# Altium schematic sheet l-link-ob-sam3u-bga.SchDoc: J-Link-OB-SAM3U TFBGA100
size A3; Revision: 2.0.0; SheetNumber: 2; SheetTotal: 3; DrawnBy: RUBR; ProjectNumber: 4393; PCAName: PCA10000; PCBRevision: 0100RUBR; DocumentSize: A2; PCBNumber: 400003
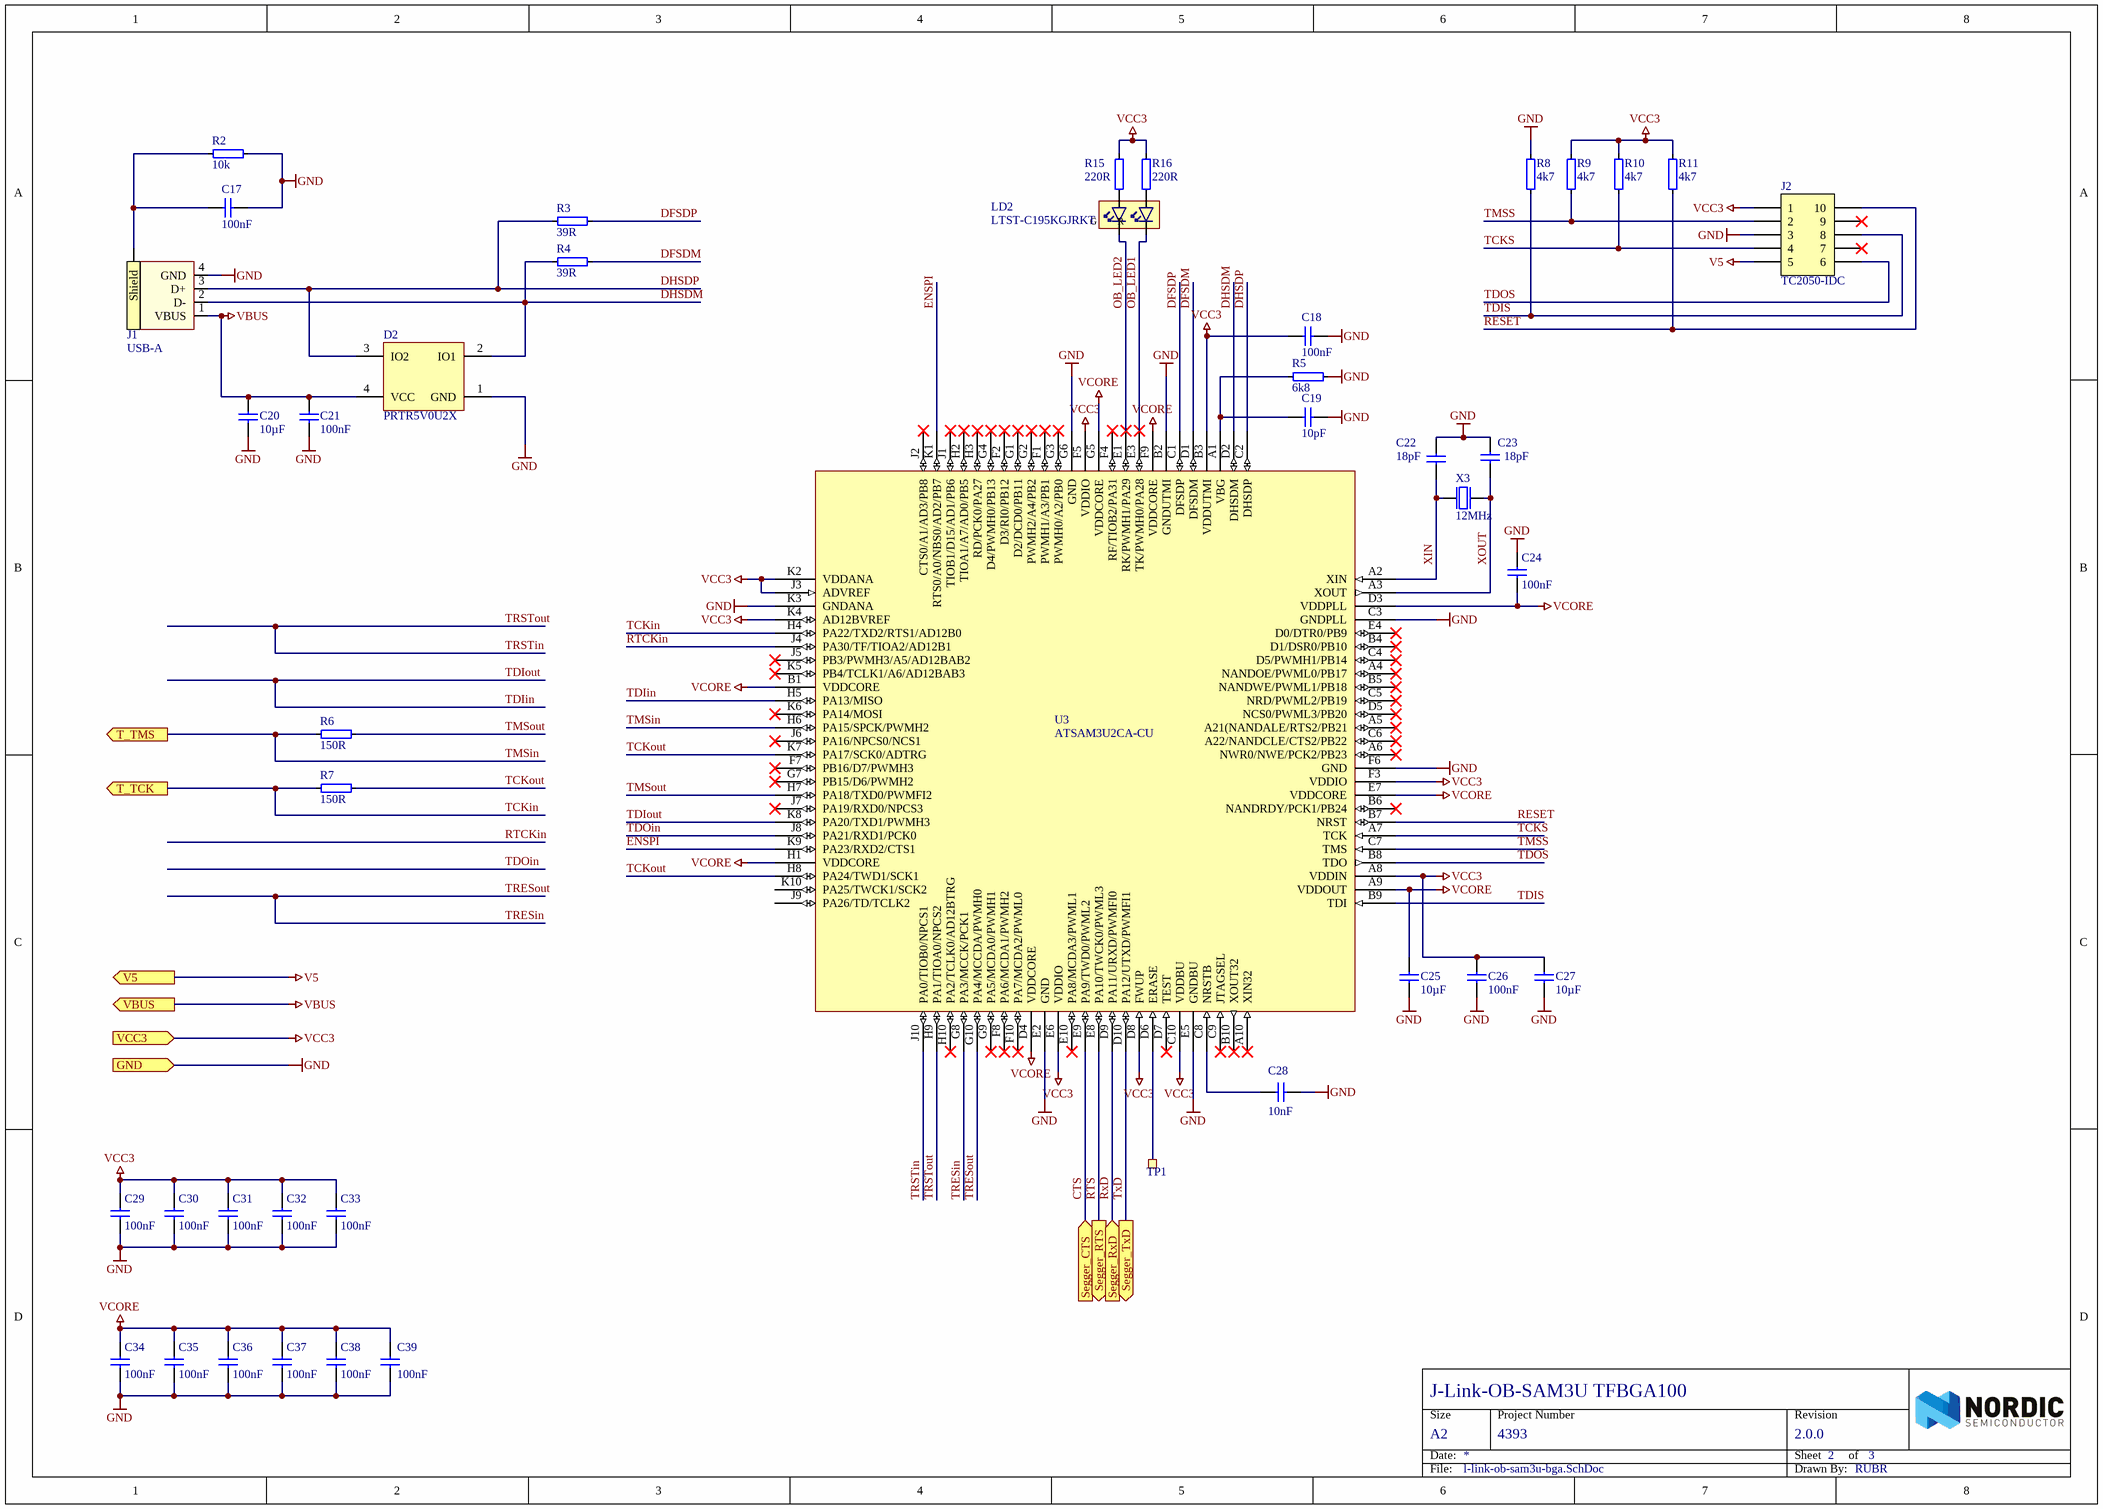
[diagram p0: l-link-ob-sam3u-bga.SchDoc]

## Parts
C17  100nF  [CAPC1005X04L]
C18  100nF  [CAPC1005X04L]
C19  10pF  [CAPC1005X04L]
C20  10µF  [CAPC1608X06L]
C21  100nF  [CAPC1005X04L]
C22  18pF  [CAPC1005X04L]
C23  18pF  [CAPC1005X04L]
C24  100nF  [CAPC1005X04L]
C25  10µF  [CAPC1608X06L]
C26  100nF  [CAPC1005X04L]
C27  10µF  [CAPC1608X06L]
C28  10nF  [CAPC1005X04L]
C29  100nF  [CAPC1005X04L]
C30  100nF  [CAPC1005X04L]
C31  100nF  [CAPC1005X04L]
C32  100nF  [CAPC1005X04L]
C33  100nF  [CAPC1005X04L]
C34  100nF  [CAPC1005X04L]
C35  100nF  [CAPC1005X04L]
C36  100nF  [CAPC1005X04L]
C37  100nF  [CAPC1005X04L]
C38  100nF  [CAPC1005X04L]
C39  100nF  [CAPC1005X04L]
D2  PRTR5V0U2X  [SOT190P230X110-4L]
J1  USB-A  [USB-PCB-A-SMD]
J2  TC2050-IDC  [TC2050-IDC-NLFP]  (no BOM)
LD2  LTST-C195KGJRKT  [LED_DUAL_0606]
R2  10k  [RESC1005X04L]
R3  39R  [RESC1005X04L]
R4  39R  [RESC1005X04L]
R5  6k8  [RESC1005X04L]
R6  150R  [RESC1005X04L]
R7  150R  [RESC1005X04L]
R8  4k7  [RESC1005X04L]
R9  4k7  [RESC1005X04L]
R10  4k7  [RESC1005X04L]
R11  4k7  [RESC1005X04L]
R15  220R  [RESC1005X04L]
R16  220R  [RESC1005X04L]
TP1  1.0mm,SMD  [TP_SMD_1.0mmX1.0mm]  (value not drawn)  (no BOM)
U3  ATSAM3U2CA-CU  [BGA100C80P10X10_900X900X110]
X3  12MHz  [BT-XTAL_3225]

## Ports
GND (in), Segger_CTS (in), Segger_RTS (out), Segger_RxD (in), Segger_TxD (out), T_TCK (out), T_TMS (out), V5 (out), VBUS (out), VCC3 (in)

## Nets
GND: C17.1 C18.1 C19.1 C20.1 C21.1 C22.2 C23.2 C24.2 C25.1 C26.1 C27.1 C28.1 C29.1 C30.1 C31.1 C32.1 C33.1 C34.1 C35.1 C36.1 C37.1 C38.1 C39.1 D2.1(GND) J1.4(GND) J2.3 R2.1 R5.1 R8.2 U3.B2(GNDUTMI) U3.C3(GNDPLL) U3.E2(GND) U3.E5(GNDBU) U3.F6(GND) U3.G6(GND) U3.K3(GNDANA) X3.2(GND) X3.4(GND) ; port GND
V5: J2.5 ; port V5
VBUS: C20.2 C21.2 D2.4(VCC) J1.1(VBUS) ; port VBUS
VCC3: C18.2 C26.2 C27.2 C29.2 C30.2 C31.2 C32.2 C33.2 J2.1 R9.2 R10.2 R11.2 R15.1 R16.1 U3.A8(VDDIN) U3.B3(VDDUTMI) U3.C10(VDDBU) U3.D8(FWUP) U3.E6(VDDIO) U3.F3(VDDIO) U3.F5(VDDIO) U3.J3(ADVREF) U3.K2(VDDANA) U3.K4(AD12BVREF) ; port VCC3
VCORE: C24.1 C25.2 C34.2 C35.2 C36.2 C37.2 C38.2 C39.2 U3.A9(VDDOUT) U3.B1(VDDCORE) U3.D3(VDDPLL) U3.D4(VDDCORE) U3.E7(VDDCORE) U3.F9(VDDCORE) U3.G5(VDDCORE) U3.H1(VDDCORE)
CTS: U3.E9(PA9/TWD0/PWML2) ; port Segger_CTS
DFSDM: R4.1 U3.D1(DFSDM)
DFSDP: R3.1 U3.C1(DFSDP)
DHSDM: D2.2(IO1) J1.2(D-) R4.2 U3.D2(DHSDM)
DHSDP: D2.3(IO2) J1.3(D+) R3.2 U3.C2(DHSDP)
ENSPI: U3.K1(RTS0/A0/NBS0/AD2/PB7) U3.K9(PA23/RXD2/CTS1)
OB_LED1: LD2.4(C1) U3.E3(TK/PWMH0/PA28)
OB_LED2: LD2.3(C2) U3.E1(RK/PWMH1/PA29)
RESET: J2.10 R11.1 U3.B7(NRST)
RTCKin: U3.J4(PA30/TF/TIOA2/AD12B1)
RTS: U3.E8(PA10/TWCK0/PWML3) ; port Segger_RTS
RxD: U3.D9(PA11/URXD/PWMFI0) ; port Segger_RxD
TCKin: R7.2 U3.H4(PA22/TXD2/RTS1/AD12B0) ; port T_TCK
TCKout: R7.1 U3.H8(PA24/TWD1/SCK1) U3.K7(PA17/SCK0/ADTRG)
TCKS: J2.4 R10.1 U3.A7(TCK)
TDIin: U3.H5(PA13/MISO) U3.K8(PA20/TXD1/PWMH3)  [also labelled TDIout]
TDIS: J2.8 R8.1 U3.B9(TDI)
TDOin: U3.J8(PA21/RXD1/PCK0)
TDOS: J2.6 U3.B8(TDO)
TMSin: R6.2 U3.H6(PA15/SPCK/PWMH2) ; port T_TMS
TMSout: R6.1 U3.H7(PA18/TXD0/PWMFI2)
TMSS: J2.2 R9.1 U3.C7(TMS)
TRESin: U3.G8(PA3/MCCK/PCK1) U3.G10(PA4/MCCDA/PWMH0)  [also labelled TRESout]
TRSTin: U3.H9(PA1/TIOA0/NPCS2) U3.J10(PA0/TIOB0/NPCS1)  [also labelled TRSTout]
TxD: U3.D10(PA12/UTXD/PWMFI1) ; port Segger_TxD
XIN: C22.1 U3.A2(XIN) X3.1(inp)
XOUT: C23.1 U3.A3(XOUT) X3.3(out)
NetC17_2: C17.2 J1.0(Shield) R2.2
NetC19_2: C19.2 R5.2 U3.A1(VBG)
NetC28_2: C28.2 U3.C8(NRSTB)
NetLD2_1: LD2.1(A2) R15.2
NetLD2_2: LD2.2(A1) R16.2
NetTP1_1: TP1.1 U3.D6(ERASE)

Not connected (* = marked no-connect by the designer): J2 7* 9*; U3 A4(NANDOE/PWML0/PB17)* A5(A21(NANDALE/RTS2/PB21)* A6(NWR0/NWE/PCK2/PB23)* A10(XIN32)* B4(D1/DSR0/PB10)* B5(NANDWE/PWML1/PB18)* B6(NANDRDY/PCK1/PB24)* B10(XOUT32)* C4(D5/PWMH1/PB14)* C5(NRD/PWML2/PB19)* C6(A22/NANDCLE/CTS2/PB22)* C9(JTAGSEL)* D5(NCS0/PWML3/PB20)* D7(TEST)* E4(D0/DTR0/PB9)* E10(PA8/MCDA3/PWML1)* F1(PWMH1/A3/PB1)* F2(D3/RI0/PB12)* F4(RF/TIOB2/PA31)* F7(PB16/D7/PWMH3)* F8(PA6/MCDA1/PWMH2)* F10(PA7/MCDA2/PWML0)* G1(D2/DCD0/PB11)* G2(PWMH2/A4/PB2)* G3(PWMH0/A2/PB0)* G4(D4/PWMH0/PB13)* G7(PB15/D6/PWMH2)* G9(PA5/MCDA0/PWMH1)* H2(TIOA1/A7/AD0/PB5)* H3(RD/PCK0/PA27)* H10(PA2/TCLK0/AD12BTRG)* J1(TIOB1/D15/AD1/PB6)* J2(CTS0/A1/AD3/PB8)* J5(PB3/PWMH3/A5/AD12BAB2)* J6(PA16/NPCS0/NCS1)* J7(PA19/RXD0/NPCS3)* J9(PA26/TD/TCLK2) K5(PB4/TCLK1/A6/AD12BAB3)* K6(PA14/MOSI)* K10(PA25/TWCK1/SCK2)

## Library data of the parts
C17 C18 C21 C24 C26 C29-C39 = C0402-100n: Capacitor, X7R, ±10%; Note: 16V; Artikkelnr Noca: 20039200
C19 = C0402-10p: Capacitor, NP0, ±2%; 2nd source part number: 185-6064; Note: 50V; Artikkelnr Noca: 20029260
C20 C25 C27 = C0603-10µ: Capacitor, X5R, ±10%; Note: 6.3V; Artikkelnr Noca: 20039252
C22 C23 = C0402-18p: Capacitor, NP0, ±5%; Note: 50V; Artikkelnr Noca: 20029209
C28 = C0402-10n: Capacitor, X7R, ±10%; Note: 16V; Artikkelnr Noca: 20039166
D2 = PRTR5V0U2X: Ultra low capacitance double rail-to-rail ESD protection diode; Manufacturer: NXP; 2nd source part number: 152-4157; Artikkelnr Noca: 10069015
J1 = Molex USB-A-SMT_w/shield: Molex USB-A-SMT; Manufacturer Part Number: 48037-1000; 2nd source part number: 538-48037-1000; Note: MOLEX - 48037-1000; Artikkelnr Noca: 55079008
J2 = TC2050-IDC-NLFP: CBL PLUG-OF-NAILS 10-PIN; Manufacturer: Tag-Connect LLC; Artikkelnr Noca: N.A.
LD2 = LTST-C195KGJRKT: Avago, HSMF-A203 Bi-Color LED; Manufacturer: Lite-On Inc; 2nd source part number: 859-LTST-C195KGJRKT; Note: HSMF-A203- xxxxx GaP Red GaP Emerald Green; Artikkelnr Noca: 13019145
R2 = R0402-10k: Resistor, ±1%, 0.063W; Note: Chip Res 1%; Artikkelnr Noca: 27049097
R3 R4 = R0402-39R: Resistor, ±1%, 0.063W; Note: Chip Res 1%; Artikkelnr Noca: 27049039
R5 = R0402-6k8: Resistor, ±1%, 0.063W; Note: Chip Res 1%; Artikkelnr Noca: 27049093
R6 R7 = R0402-150: Resistor, ±1%, 0.063W; Note: Chip Res 1%; Artikkelnr Noca: 27049053
R8-R11 = R0402-4k7: Resistor, ±1%, 0.063W; Note: Chip Res 1%; Artikkelnr Noca: 27049089
R15 R16 = R0402-220: Resistor, ±1%, 0.063W; Note: Chip Res 1%; Artikkelnr Noca: 27049057
TP1 = TP_SMD_1.0MM: Regular Plated, 1.0mm hole; Manufacturer: Nordic Semiconductor; Artikkelnr Noca: N.A.
U3 = ATSAM3U2CA-CU: IC MCU 32bit 128kB flash 100TFBGA; Manufacturer: Atmel; 2nd source part number: 556-ATSAM3U2CA-CU; Artikkelnr Noca: 15019072
X3 = XTAL SMD 12MHz (3225): XTAL SMD 3225, 12MHz, 18pF, ±30ppm; Manufacturer: TXC Corporation; Manufacturer Part Number: 7M-12.000MAAJ-T; 2nd source part number: 184-2056; Note: XTAL SMD 12.000MHz; Artikkelnr Noca: 22019166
